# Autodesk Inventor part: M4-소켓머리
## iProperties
IsCustomPart: 0
Created: 2009-02
Part Number: M4-소켓머리
Material: 강, 연강
Description: 6각머리 태핑 나사
Document SubType Name: Modeling
Standard: KS B 1003
Designer: 한국산업디자인학원 [http://gmhk.co.kr]
Standards Organization: KS
Language: ko-KR
Size Designation: M 4 x 12
Categories: <MemberInstance><Categories><Category DisplayName="조임쇠" InternalName="e4da775c-781d-43d5-af7c-5136215cf5a6" Mnemonic="FSTN"><Category DisplayName="볼트" InternalN
Density: 1 g/cm^3
Author: pww
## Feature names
1. Fillet2
